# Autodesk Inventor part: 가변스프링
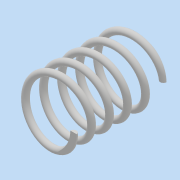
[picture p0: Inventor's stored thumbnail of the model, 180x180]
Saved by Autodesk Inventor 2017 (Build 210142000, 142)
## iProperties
Part Number: 가변스프링
Material: 일반
Document SubType Name: Modeling
Designer: MRC
Density: 1 g/cm^3
Appearance: 기본값
Mass: 0.874837 g
Surface Area: 17.7558 cm^2
Volume: 0.874837 cm^3
Author: MRC
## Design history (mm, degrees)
sketch "스케치1"
  geometry: L1 (0, 0)-(0, 28.5); L2 (0, 0)-(9, 0); L3 (0, 28.5)-(9, 28.5); C1 r 1 at (9, 0)
  constraints: 6 end point, 2 horizontal, 1 centre point, 1 coincident, 1 parallel, 1 vertical
  dimensions: "d0" = 9 distance of L1.start L2.end; "d1" = 2 diameter of C1; "d4" = 28.5 distance of L1.start L1.end (derived)
feature "코일1" sketch "스케치1" pitch "d5" = 5; turns "d7" = 5; dims "d6" = 28.5 (= d4), "d8" = 0, angle "d9" = 90 deg, angle "d10" = 90 deg, "d11" = 0, "d12" = 0
sketch "스케치2"
  geometry: L1 (0, -12.5)-(28.5, -12.5); L2 (28.5, -12.5)-(28.5, 12.5); L3 (28.5, 12.5)-(0, 12.5); L4 (0, 12.5)-(0, -12.5); 2 further points
  constraints: 8 end point, 2 midpoint, 2 parallel, 1 horizontal, 1 horizontal alignment, 1 perpendicular
  dimensions: "d13" = 25 distance of L1.end L2.end; "d14" = 28.5 distance of L1.start L1.end (= d4)
extrude "돌출1" sketch "스케치2" stored distance "d15" = 25; taper "d16" = 0 deg
node "솔리드1"
